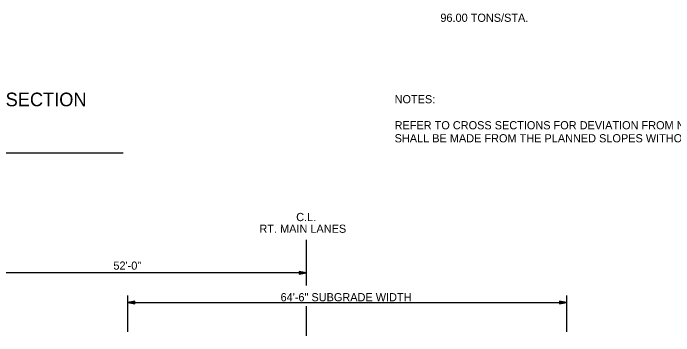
# Model space of a CAD drawing. Extents: x 1734743 to 1735935, y 759845 to 763831.
# Drawn here: x 1735766.6 to 1735863.7, y 760623.7 to 760671.1 of the extents above; entities that cross this region are included whole.
import ezdxf

# ---------------------------------------------------------------- set-up
doc = ezdxf.new("R2010")
doc.units = 0
doc.layers.add('1', color=7, linetype='Continuous')
doc.layers.add('19', color=7, linetype='Continuous')

msp = doc.modelspace()

# ---------------------------------------------------------------- linework, layer by layer
at = {"layer": '19'}
for p, q in [((1735723.158, 760650.611), (1735782.795, 760650.611)), ((1735809.701, 760631.103), (1735809.701, 760637.832)), ((1735809.701, 760632.991), (1735757.701, 760632.991)), ((1735808.651, 760633.175), (1735808.651, 760632.808)), ((1735809.701, 760632.991), (1735808.651, 760633.175)), ((1735809.421, 760633.018), (1735808.651, 760633.079)), ((1735808.651, 760632.808), (1735809.701, 760632.991)), ((1735808.651, 760632.895), (1735809.421, 760632.965)), ((1735783.456, 760624.31), (1735783.456, 760629.669)), ((1735847.97, 760624.31), (1735847.97, 760629.669)), ((1735784.506, 760628.807), (1735783.456, 760628.623)), ((1735783.456, 760628.623), (1735784.506, 760628.439)), ((1735783.456, 760628.623), (1735847.97, 760628.623)), ((1735784.506, 760628.71), (1735783.736, 760628.649)), ((1735783.736, 760628.597), (1735784.506, 760628.527)), ((1735784.506, 760628.439), (1735784.506, 760628.807)), ((1735809.721, 760623.747), (1735809.721, 760628.1)), ((1735846.92, 760628.807), (1735846.92, 760628.439)), ((1735847.97, 760628.623), (1735846.92, 760628.807)), ((1735847.69, 760628.649), (1735846.92, 760628.711)), ((1735846.92, 760628.439), (1735847.97, 760628.623)), ((1735846.92, 760628.527), (1735847.69, 760628.597))]:
    msp.add_line(p, q, dxfattribs=at)

# ---------------------------------------------------------------- texts
at = {"layer": '1'}
for s, p in [('NOTES:', (1735822.67, 760657.872)), ('REFER TO CROSS SECTIONS FOR DEVIATION FROM NORMAL SLOPES. NO CHANGES', (1735822.67, 760654.049)), ('SHALL BE MADE FROM THE PLANNED SLOPES WITHOUT THE APPROVAL OF THE ENGINEER.', (1735822.67, 760652.137))]:
    msp.add_text(s, height=1.2, dxfattribs=at).set_placement(p)
at = {"layer": '19'}
msp.add_text('96.00 TONS/STA.', height=1.2, rotation=360, dxfattribs=at).set_placement((1735829.393, 760669.828))
for s, height, p in [('I-57 TYPICAL DIVIDED HIGHWAY SECTION', 2, (1735723.158, 760657.437)), ('C.L.', 1.2, (1735808.208, 760640.578)), ('RT. MAIN LANES', 1.2, (1735802.803, 760638.862)), ('52\'-0"', 1.2, (1735781.347, 760633.448)), ('64\'-6" SUBGRADE WIDTH', 1.2, (1735805.913, 760628.808))]:
    msp.add_text(s, height=height, dxfattribs=at).set_placement(p)

doc.saveas('drawing.dxf')
